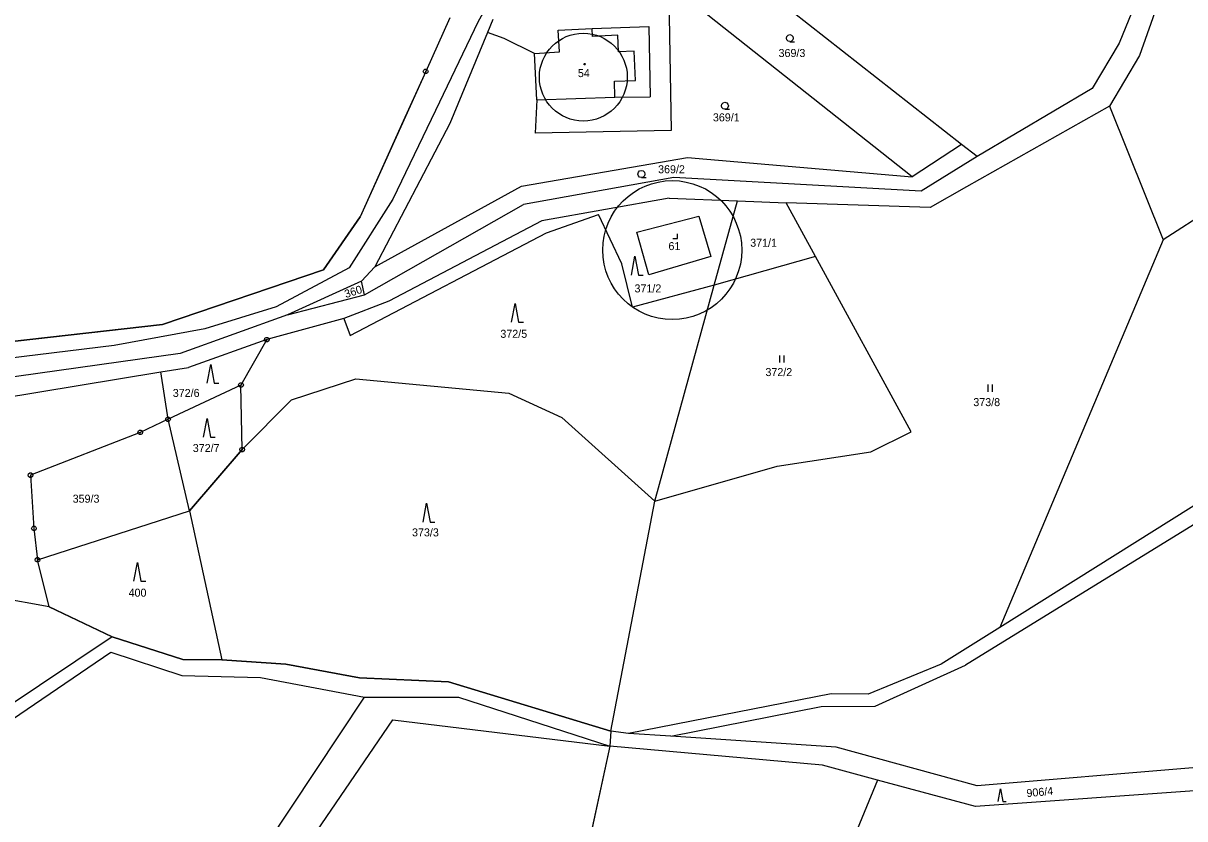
# Model space of a CAD drawing. Extents: x -580551 to -575069, y -1073031 to -1067931.
# Drawn here: x -577624.4 to -577377.7, y -1070260.5 to -1070091.5 of the extents above; entities that cross this region are included whole.
import ezdxf

# ---------------------------------------------------------------- set-up
doc = ezdxf.new("R2010")
doc.units = 0
for name, color, linetype in [('Druh pozemku', 7, 'Continuous'), ('Geodetické body', 7, 'Continuous'), ('Hranice z DKM', 7, 'Continuous'), ('Katastrální hranice', 7, 'Continuous'), ('Parcela', 7, 'Continuous'), ('Parcelní číslo', 7, 'Continuous'), ('Parcelní číslo_stavba', 7, 'Continuous'), ('stavební parcely', 7, 'Continuous'), ('Vnitřní kresba', 7, 'Continuous'), ('Vrstva 6', 7, 'Continuous'), ('ČR - rámy ML', 7, 'Continuous')]:
    doc.layers.add(name, color=color, linetype=linetype)

msp = doc.modelspace()

# ---------------------------------------------------------------- linework, layer by layer
at = {"layer": 'Druh pozemku'}
for p, q in [((-577463.8, -1070162.11), (-577463.8, -1070163.61)), ((-577462.8, -1070163.61), (-577462.8, -1070162.11)), ((-577419.54, -1070168.29), (-577419.54, -1070169.79)), ((-577418.54, -1070169.79), (-577418.54, -1070168.29))]:
    msp.add_line(p, q, dxfattribs=at)
for points in [[(-577461.57, -1070095.44), (-577461.95, -1070095.34), (-577462.22, -1070095.07), (-577462.32, -1070094.7), (-577462.22, -1070094.33), (-577461.95, -1070094.06), (-577461.58, -1070093.96), (-577461.21, -1070094.06), (-577460.94, -1070094.33), (-577460.84, -1070094.71), (-577460.94, -1070095.09), (-577461.21, -1070095.36), (-577461.59, -1070095.46), (-577460.59, -1070095.46)], [(-577475.35, -1070109.8), (-577475.73, -1070109.7), (-577476, -1070109.43), (-577476.1, -1070109.06), (-577476, -1070108.69), (-577475.73, -1070108.42), (-577475.36, -1070108.32), (-577474.99, -1070108.42), (-577474.72, -1070108.69), (-577474.62, -1070109.07), (-577474.72, -1070109.45), (-577474.99, -1070109.72), (-577475.37, -1070109.82), (-577474.37, -1070109.82)], [(-577493.1, -1070124.3), (-577493.48, -1070124.2), (-577493.75, -1070123.93), (-577493.85, -1070123.56), (-577493.75, -1070123.19), (-577493.48, -1070122.92), (-577493.11, -1070122.82), (-577492.74, -1070122.92), (-577492.47, -1070123.19), (-577492.37, -1070123.57), (-577492.47, -1070123.95), (-577492.74, -1070124.22), (-577493.12, -1070124.32), (-577492.12, -1070124.32)], [(-577486.45, -1070137.29), (-577485.45, -1070137.29), (-577485.45, -1070136.29)], [(-577495.24, -1070145.02), (-577494.49, -1070141.02), (-577493.74, -1070145.02), (-577492.74, -1070145.02)], [(-577520.68, -1070155.05), (-577519.93, -1070151.05), (-577519.18, -1070155.05), (-577518.18, -1070155.05)], [(-577585.34, -1070168.01), (-577584.59, -1070164.01), (-577583.84, -1070168.01), (-577582.84, -1070168.01)], [(-577586.11, -1070179.48), (-577585.36, -1070175.48), (-577584.61, -1070179.48), (-577583.61, -1070179.48)], [(-577539.49, -1070197.49), (-577538.74, -1070193.49), (-577537.99, -1070197.49), (-577536.99, -1070197.49)], [(-577600.9, -1070210.04), (-577600.15, -1070206.04), (-577599.4, -1070210.04), (-577598.4, -1070210.04)], [(-577417.312, -1070256.82), (-577416.81, -1070254.14), (-577416.308, -1070256.82), (-577415.638, -1070256.82)]]:
    msp.add_lwpolyline(points, dxfattribs=at)
msp.add_lwpolyline([(-577505.09, -1070100.09), (-577505, -1070100.24), (-577505.09, -1070100.39), (-577505.27, -1070100.39), (-577505.36, -1070100.24), (-577505.27, -1070100.09)], close=True, dxfattribs=at)
at = {"layer": 'Geodetické body'}
for p, q in [((-577539.05, -1070101.78), (-577538.81, -1070101.78)), ((-577572.78, -1070158.74), (-577572.54, -1070158.74)), ((-577578.28, -1070168.38), (-577578.04, -1070168.38)), ((-577593.77, -1070175.66), (-577593.53, -1070175.66)), ((-577599.67, -1070178.44), (-577599.43, -1070178.44)), ((-577578.03, -1070182.1), (-577577.79, -1070182.1)), ((-577622.97, -1070187.53), (-577622.73, -1070187.53)), ((-577622.25, -1070198.84), (-577622.01, -1070198.84)), ((-577621.51, -1070205.49), (-577621.27, -1070205.49))]:
    msp.add_line(p, q, dxfattribs=at)
for points in [[(-577538.78, -1070101.3), (-577538.53, -1070101.48), (-577538.43, -1070101.77), (-577538.53, -1070102.06), (-577538.78, -1070102.24), (-577539.09, -1070102.24), (-577539.34, -1070102.06), (-577539.44, -1070101.77), (-577539.34, -1070101.48), (-577539.09, -1070101.3)], [(-577572.51, -1070158.26), (-577572.26, -1070158.44), (-577572.16, -1070158.73), (-577572.26, -1070159.02), (-577572.51, -1070159.2), (-577572.82, -1070159.2), (-577573.07, -1070159.02), (-577573.17, -1070158.73), (-577573.07, -1070158.44), (-577572.82, -1070158.26)], [(-577578.01, -1070167.9), (-577577.76, -1070168.08), (-577577.66, -1070168.37), (-577577.76, -1070168.66), (-577578.01, -1070168.84), (-577578.32, -1070168.84), (-577578.57, -1070168.66), (-577578.67, -1070168.37), (-577578.57, -1070168.08), (-577578.32, -1070167.9)], [(-577593.5, -1070175.18), (-577593.25, -1070175.36), (-577593.15, -1070175.65), (-577593.25, -1070175.94), (-577593.5, -1070176.12), (-577593.81, -1070176.12), (-577594.06, -1070175.94), (-577594.16, -1070175.65), (-577594.06, -1070175.36), (-577593.81, -1070175.18)], [(-577599.4, -1070177.96), (-577599.15, -1070178.14), (-577599.05, -1070178.43), (-577599.15, -1070178.72), (-577599.4, -1070178.9), (-577599.71, -1070178.9), (-577599.96, -1070178.72), (-577600.06, -1070178.43), (-577599.96, -1070178.14), (-577599.71, -1070177.96)], [(-577577.76, -1070181.62), (-577577.51, -1070181.8), (-577577.41, -1070182.09), (-577577.51, -1070182.38), (-577577.76, -1070182.56), (-577578.07, -1070182.56), (-577578.32, -1070182.38), (-577578.42, -1070182.09), (-577578.32, -1070181.8), (-577578.07, -1070181.62)], [(-577622.7, -1070187.05), (-577622.45, -1070187.23), (-577622.35, -1070187.52), (-577622.45, -1070187.81), (-577622.7, -1070187.99), (-577623.01, -1070187.99), (-577623.26, -1070187.81), (-577623.36, -1070187.52), (-577623.26, -1070187.23), (-577623.01, -1070187.05)], [(-577621.98, -1070198.36), (-577621.73, -1070198.54), (-577621.63, -1070198.83), (-577621.73, -1070199.12), (-577621.98, -1070199.3), (-577622.29, -1070199.3), (-577622.54, -1070199.12), (-577622.64, -1070198.83), (-577622.54, -1070198.54), (-577622.29, -1070198.36)], [(-577621.24, -1070205.01), (-577620.99, -1070205.19), (-577620.89, -1070205.48), (-577620.99, -1070205.77), (-577621.24, -1070205.95), (-577621.55, -1070205.95), (-577621.8, -1070205.77), (-577621.9, -1070205.48), (-577621.8, -1070205.19), (-577621.55, -1070205.01)]]:
    msp.add_lwpolyline(points, close=True, dxfattribs=at)
at = {"layer": 'Hranice z DKM'}
for p, q in [((-577577.91, -1070182.1), (-577589.12, -1070195.09)), ((-577499.59, -1070241.87), (-577490.23, -1070193.03)), ((-577591.12, -1070293.63), (-577551.94, -1070234.66))]:
    msp.add_line(p, q, dxfattribs=at)
for points in [[(-577733.21, -1070206.16), (-577730.17, -1070215), (-577717.15, -1070226.85), (-577639.89, -1070243.42), (-577631.86, -1070240.34), (-577628.45, -1070240.53), (-577605.81, -1070225.09), (-577590.71, -1070230.06), (-577574, -1070230.49), (-577551.94, -1070234.66)], [(-577230.43, -1070211.87), (-577283.44, -1070225.49), (-577359.72, -1070246.97), (-577375.98, -1070249.68), (-577421.77, -1070253.5), (-577451.74, -1070245.29), (-577486.84, -1070242.99)], [(-577618.91, -1070215.5), (-577605.5, -1070221.86), (-577590.49, -1070226.65), (-577582.24, -1070226.78)], [(-577582.24, -1070226.78), (-577568.61, -1070227.64), (-577552.99, -1070230.58), (-577534.06, -1070231.4), (-577499.59, -1070241.87)], [(-577551.94, -1070234.66), (-577531.97, -1070234.7), (-577499.81, -1070245.09)], [(-577499.81, -1070245.09), (-577506.24, -1070274.73), (-577509.29, -1070302.79)]]:
    msp.add_lwpolyline(points, dxfattribs=at)
at = {"layer": 'Katastrální hranice'}
for p, q in [((-577533.81, -1070090.41), (-577538.93, -1070101.78)), ((-577538.93, -1070101.78), (-577552.86, -1070132.66)), ((-577560.66, -1070143.93), (-577552.86, -1070132.66)), ((-577594.83, -1070155.52), (-577560.66, -1070143.93)), ((-577643.78, -1070161.04), (-577594.83, -1070155.52))]:
    msp.add_line(p, q, dxfattribs=at)
at = {"layer": 'Parcela'}
for p, q in [((-577425.08, -1070117.28), (-577487.4, -1070068.3)), ((-577487.34, -1070083.18), (-577486.78, -1070114.29)), ((-577435.61, -1070124.15), (-577487.34, -1070083.18)), ((-577386.61, -1070083.56), (-577391.64, -1070095.76)), ((-577383.27, -1070086.96), (-577387.33, -1070098.38)), ((-577524.68, -1070090.71), (-577525.83, -1070093.49)), ((-577525.83, -1070093.49), (-577533.78, -1070112.8)), ((-577522.27, -1070094.75), (-577525.83, -1070093.49)), ((-577515.83, -1070097.94), (-577522.27, -1070094.75)), ((-577391.64, -1070095.76), (-577397.36, -1070105.43)), ((-577515.29, -1070107.78), (-577515.83, -1070097.94)), ((-577387.33, -1070098.38), (-577393.66, -1070109.16)), ((-577397.36, -1070105.43), (-577421.82, -1070119.84)), ((-577515.29, -1070107.78), (-577515.65, -1070114.85)), ((-577393.66, -1070109.16), (-577424.07, -1070126.31)), ((-577533.78, -1070112.8), (-577549.73, -1070143.27)), ((-577486.78, -1070114.29), (-577515.65, -1070114.85)), ((-577425.08, -1070117.28), (-577435.61, -1070124.15)), ((-577421.82, -1070119.84), (-577425.08, -1070117.28)), ((-577518.61, -1070126.17), (-577483.3, -1070120.04)), ((-577483.3, -1070120.04), (-577435.61, -1070124.15)), ((-577421.82, -1070119.84), (-577433.66, -1070127.22)), ((-577549.73, -1070143.27), (-577518.61, -1070126.17)), ((-577486.23, -1070124.29), (-577518.14, -1070130.01)), ((-577433.66, -1070127.22), (-577486.23, -1070124.29)), ((-577424.07, -1070126.31), (-577431.78, -1070130.66)), ((-577487.19, -1070128.69), (-577514.25, -1070133.48)), ((-577487.19, -1070128.69), (-577472.7, -1070129.28)), ((-577551.94, -1070149.25), (-577518.14, -1070130.01)), ((-577477.62, -1070147.17), (-577472.7, -1070129.28)), ((-577472.7, -1070129.28), (-577462.35, -1070129.71)), ((-577456.13, -1070141.09), (-577462.35, -1070129.71)), ((-577431.78, -1070130.66), (-577462.35, -1070129.71)), ((-577514.25, -1070133.48), (-577546.76, -1070150.59)), ((-577513.29, -1070136.06), (-577502.24, -1070132.19)), ((-577497.23, -1070142.65), (-577502.24, -1070132.19)), ((-577494.07, -1070135.91), (-577480.92, -1070132.53)), ((-577480.92, -1070132.53), (-577478.35, -1070141.07)), ((-577554.97, -1070157.83), (-577513.29, -1070136.06)), ((-577491.5, -1070144.94), (-577494.07, -1070135.91)), ((-577478.35, -1070141.07), (-577491.5, -1070144.94)), ((-577456.13, -1070141.09), (-577477.62, -1070147.17)), ((-577435.78, -1070178.35), (-577456.13, -1070141.09)), ((-577549.73, -1070143.27), (-577552.53, -1070146.33)), ((-577494.99, -1070151.83), (-577497.23, -1070142.65)), ((-577552.53, -1070146.33), (-577568.25, -1070153.48)), ((-577551.94, -1070149.25), (-577552.53, -1070146.33)), ((-577477.62, -1070147.17), (-577494.99, -1070151.83)), ((-577490.23, -1070193.03), (-577477.62, -1070147.17)), ((-577568.25, -1070153.48), (-577551.94, -1070149.25)), ((-577546.76, -1070150.59), (-577556.29, -1070154.24)), ((-577568.25, -1070153.48), (-577591.09, -1070161.69)), ((-577556.29, -1070154.24), (-577572.66, -1070158.74)), ((-577556.29, -1070154.24), (-577554.97, -1070157.83)), ((-577572.66, -1070158.74), (-577589.32, -1070164.64)), ((-577572.66, -1070158.74), (-577578.16, -1070168.38)), ((-577591.09, -1070161.69), (-577642.6, -1070168.95)), ((-577651.06, -1070174.81), (-577595.15, -1070165.6)), ((-577595.15, -1070165.6), (-577589.32, -1070164.64)), ((-577593.65, -1070175.66), (-577595.15, -1070165.6)), ((-577328.4, -1070164.3), (-577416.99, -1070219.9)), ((-577578.16, -1070168.38), (-577593.65, -1070175.66)), ((-577577.91, -1070182.1), (-577578.16, -1070168.38)), ((-577567.46, -1070171.53), (-577553.75, -1070167.05)), ((-577553.75, -1070167.05), (-577521.26, -1070170.09)), ((-577325.82, -1070167.19), (-577424.28, -1070227.9)), ((-577521.26, -1070170.09), (-577509.99, -1070175.29)), ((-577577.91, -1070182.1), (-577567.46, -1070171.53)), ((-577593.65, -1070175.66), (-577599.55, -1070178.44)), ((-577589.12, -1070195.09), (-577593.65, -1070175.66)), ((-577509.99, -1070175.29), (-577490.23, -1070193.03)), ((-577599.55, -1070178.44), (-577622.85, -1070187.53)), ((-577444.34, -1070182.54), (-577435.78, -1070178.35)), ((-577589.12, -1070195.09), (-577577.91, -1070182.1)), ((-577464.27, -1070185.64), (-577444.34, -1070182.54)), ((-577490.23, -1070193.03), (-577464.27, -1070185.64)), ((-577622.85, -1070187.53), (-577622.13, -1070198.84)), ((-577499.59, -1070241.87), (-577490.23, -1070193.03)), ((-577621.39, -1070205.49), (-577589.12, -1070195.09)), ((-577589.12, -1070195.09), (-577582.24, -1070226.78)), ((-577622.13, -1070198.84), (-577621.39, -1070205.49)), ((-577618.91, -1070215.5), (-577621.39, -1070205.49)), ((-577618.91, -1070215.5), (-577641.2, -1070211.41)), ((-577605.5, -1070221.86), (-577618.91, -1070215.5)), ((-577416.99, -1070219.9), (-577429.41, -1070227.69)), ((-577605.5, -1070221.86), (-577628.69, -1070237.37)), ((-577590.49, -1070226.65), (-577605.5, -1070221.86)), ((-577628.45, -1070240.53), (-577605.81, -1070225.09)), ((-577605.81, -1070225.09), (-577590.71, -1070230.06)), ((-577582.24, -1070226.78), (-577590.49, -1070226.65)), ((-577568.61, -1070227.64), (-577582.24, -1070226.78)), ((-577552.99, -1070230.58), (-577568.61, -1070227.64)), ((-577429.41, -1070227.69), (-577444.92, -1070234.01)), ((-577443.47, -1070236.59), (-577424.28, -1070227.9)), ((-577590.71, -1070230.06), (-577574, -1070230.49)), ((-577574, -1070230.49), (-577551.94, -1070234.66)), ((-577534.06, -1070231.4), (-577552.99, -1070230.58)), ((-577499.59, -1070241.87), (-577534.06, -1070231.4)), ((-577591.12, -1070293.63), (-577551.94, -1070234.66)), ((-577551.94, -1070234.66), (-577531.97, -1070234.7)), ((-577531.97, -1070234.7), (-577499.81, -1070245.09)), ((-577452.77, -1070233.95), (-577495.86, -1070242.41)), ((-577444.92, -1070234.01), (-577452.77, -1070233.95)), ((-577486.84, -1070242.99), (-577454.95, -1070236.67)), ((-577454.95, -1070236.67), (-577443.47, -1070236.59)), ((-577581.85, -1070292.21), (-577545.93, -1070239.47)), ((-577545.93, -1070239.47), (-577499.81, -1070245.09)), ((-577495.86, -1070242.41), (-577499.59, -1070241.87)), ((-577486.84, -1070242.99), (-577495.86, -1070242.41)), ((-577499.81, -1070245.09), (-577506.24, -1070274.73)), ((-577454.66, -1070249.14), (-577499.81, -1070245.09)), ((-577451.74, -1070245.29), (-577486.84, -1070242.99)), ((-577421.77, -1070253.5), (-577451.74, -1070245.29)), ((-577442.96, -1070252.28), (-577454.66, -1070249.14)), ((-577375.98, -1070249.68), (-577421.77, -1070253.5)), ((-577442.96, -1070252.28), (-577450.77, -1070271.31)), ((-577422.11, -1070257.88), (-577442.96, -1070252.28)), ((-577373.64, -1070254.41), (-577422.11, -1070257.88))]:
    msp.add_line(p, q, dxfattribs=at)
at = {"layer": 'Parcelní číslo'}
for points in [[(-577424.957, -1069929.888), (-577436.357, -1069938.804), (-577445.685, -1069946.1), (-577457.584, -1069958.078), (-577463.35, -1069966.207), (-577468.984, -1069976.565), (-577476.977, -1069998.462), (-577487.198, -1070020.752), (-577495.322, -1070033.732), (-577515.108, -1070068.74), (-577527.789, -1070091.178), (-577536.86, -1070110.042), (-577545.93, -1070128.906), (-577555.204, -1070143.477), (-577570.666, -1070151.737)], [(-577570.666, -1070151.737), (-577585.866, -1070156.457), (-577605.128, -1070159.997), (-577631.204, -1070163.144), (-577642.235, -1070164.476), (-577663.307, -1070170.749), (-577678.507, -1070177.043), (-577685.714, -1070182.287), (-577687.405, -1070183.518)]]:
    msp.add_lwpolyline(points, dxfattribs=at)
at = {"layer": 'stavební parcely'}
for centre, radius in [((-577505.44, -1070102.98), 9.335), ((-577486.55, -1070139.72), 14.761)]:
    msp.add_circle(centre, radius, dxfattribs=at)
at = {"layer": 'Vnitřní kresba'}
for p, q in [((-577503.59, -1070092.62), (-577491.5, -1070092.2)), ((-577491.5, -1070092.2), (-577491.21, -1070107.15)), ((-577510.78, -1070092.98), (-577503.59, -1070092.62)), ((-577510.53, -1070097.63), (-577510.78, -1070092.98)), ((-577503.51, -1070094.33), (-577503.59, -1070092.62)), ((-577498.12, -1070094.08), (-577503.51, -1070094.33)), ((-577497.96, -1070097.58), (-577498.12, -1070094.08)), ((-577515.83, -1070097.94), (-577510.53, -1070097.63)), ((-577494.62, -1070097.44), (-577497.96, -1070097.58)), ((-577494.37, -1070103.67), (-577494.62, -1070097.44)), ((-577498.81, -1070103.85), (-577494.37, -1070103.67)), ((-577498.73, -1070107.22), (-577498.81, -1070103.85)), ((-577515.29, -1070107.78), (-577498.73, -1070107.22)), ((-577498.73, -1070107.22), (-577491.21, -1070107.15))]:
    msp.add_line(p, q, dxfattribs=at)
at = {"layer": 'Vrstva 6'}
for p, q in [((-577393.66, -1070109.16), (-577382.3, -1070137.57)), ((-577343.16, -1070112.14), (-577382.3, -1070137.57)), ((-577382.3, -1070137.57), (-577416.99, -1070219.9)), ((-577499.59, -1070241.87), (-577499.81, -1070245.09))]:
    msp.add_line(p, q, dxfattribs=at)
at = {"layer": 'ČR - rámy ML'}
msp.add_lwpolyline([(-577533.81, -1070090.41), (-577538.93, -1070101.78), (-577544.05, -1070113.15), (-577552.86, -1070132.66), (-577560.66, -1070143.93), (-577594.83, -1070155.52), (-577643.78, -1070161.04), (-577650.78, -1070163.15), (-577670.45, -1070168.16), (-577671.813, -1070168.882)], dxfattribs=at)

# ---------------------------------------------------------------- texts
at = {"layer": 'Parcelní číslo'}
for s, p in [('369/3', (-577463.973, -1070098.71)), ('369/1', (-577477.919, -1070112.38)), ('369/2', (-577489.561, -1070123.4)), ('371/1', (-577469.996, -1070139.01)), ('371/2', (-577494.569, -1070148.71)), ('372/5', (-577523.067, -1070158.35)), ('372/2', (-577466.761, -1070166.48)), ('372/6', (-577592.646, -1070170.91)), ('373/8', (-577422.605, -1070172.86)), ('372/7', (-577588.4, -1070182.61)), ('359/3', (-577613.914, -1070193.37)), ('373/3', (-577541.824, -1070200.53)), ('400', (-577602.031, -1070213.34))]:
    msp.add_text(s, height=1.7, dxfattribs=at).set_placement(p)
for s, rotation, p in [('360', 17.76169, (-577555.878, -1070149.927)), ('906/4', 5.04203, (-577411.241, -1070255.918))]:
    msp.add_text(s, height=1.7, rotation=rotation, dxfattribs=at).set_placement(p)
at = {"layer": 'Parcelní číslo_stavba'}
for s, p in [('54', (-577506.597, -1070102.98)), ('61', (-577487.359, -1070139.72))]:
    msp.add_text(s, height=1.7, dxfattribs=at).set_placement(p)

doc.saveas('drawing.dxf')
